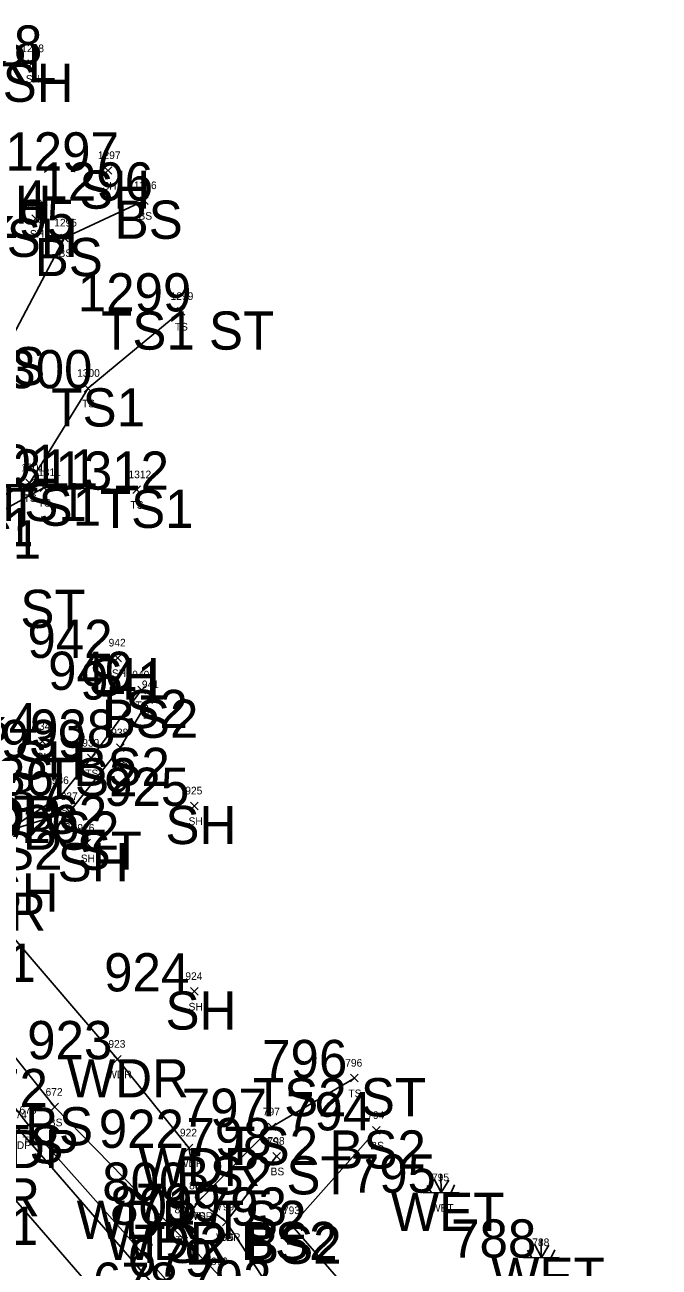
# Model space of a CAD drawing. Extents: x 1616840 to 1618410, y 488554 to 491945.
# Drawn here: x 1617896.5 to 1618062.6, y 488979.2 to 489304.3 of the extents above; entities that cross this region are included whole.
import ezdxf

# ---------------------------------------------------------------- set-up
doc = ezdxf.new("R2010")
doc.units = 0
for name, color, linetype in [('C_A', 7, 'Continuous'), ('C_I', 7, 'Continuous'), ('L_A', 7, 'Continuous'), ('L_I', 7, 'Continuous'), ('L_TIC', 7, 'Continuous'), ('LAWA', 7, 'Continuous'), ('LELB', 7, 'Continuous'), ('LWET', 7, 'Continuous'), ('P_A', 7, 'Continuous'), ('P_I', 7, 'Continuous'), ('PET', 7, 'Continuous'), ('PRC', 7, 'Continuous')]:
    doc.layers.add(name, color=color, linetype=linetype)

msp = doc.modelspace()

# ---------------------------------------------------------------- linework, layer by layer
at = {"layer": 'L_TIC'}
for points in [[(1617897.27, 489293.2), (1617899.27, 489295.2)], [(1617899.27, 489293.2), (1617897.27, 489295.2)], [(1617917.32, 489265.23), (1617919.32, 489267.23)], [(1617919.32, 489265.23), (1617917.32, 489267.23)], [(1617926.82, 489257.36), (1617928.82, 489259.36)], [(1617928.82, 489257.36), (1617926.82, 489259.36)], [(1617898.33, 489252.62), (1617900.33, 489254.62)], [(1617900.33, 489252.62), (1617898.33, 489254.62)], [(1617905.89, 489247.58), (1617907.89, 489249.58)], [(1617907.89, 489247.58), (1617905.89, 489249.58)], [(1617936.38, 489228.35), (1617938.38, 489230.35)], [(1617938.38, 489228.35), (1617936.38, 489230.35)], [(1617912.05, 489208.24), (1617914.05, 489210.24)], [(1617914.05, 489208.24), (1617912.05, 489210.24)], [(1617896.8, 489183.49), (1617898.8, 489185.49)], [(1617898.8, 489183.49), (1617896.8, 489185.49)], [(1617900.54, 489182.26), (1617902.54, 489184.26)], [(1617902.54, 489182.26), (1617900.54, 489184.26)], [(1617924.77, 489181.7), (1617926.77, 489183.7)], [(1617926.77, 489181.7), (1617924.77, 489183.7)], [(1617919.82, 489137.67), (1617921.82, 489139.67)], [(1617921.82, 489137.67), (1617919.82, 489139.67)], [(1617926.08, 489129.32), (1617928.08, 489131.32)], [(1617928.08, 489129.32), (1617926.08, 489131.32)], [(1617927.95, 489126.77), (1617929.95, 489128.77)], [(1617929.95, 489126.77), (1617927.95, 489128.77)], [(1617900.09, 489115.84), (1617902.09, 489117.84)], [(1617902.09, 489115.84), (1617900.09, 489117.84)], [(1617912.91, 489111.46), (1617914.91, 489113.46)], [(1617914.91, 489111.46), (1617912.91, 489113.46)], [(1617920.49, 489114.18), (1617922.49, 489116.18)], [(1617922.49, 489114.18), (1617920.49, 489116.18)], [(1617904.98, 489101.66), (1617906.98, 489103.66)], [(1617906.98, 489101.66), (1617904.98, 489103.66)], [(1617939.88, 489098.96), (1617941.88, 489100.96)], [(1617941.88, 489098.96), (1617939.88, 489100.96)], [(1617907.26, 489097.48), (1617909.26, 489099.48)], [(1617909.26, 489097.48), (1617907.26, 489099.48)], [(1617911.68, 489089.21), (1617913.68, 489091.21)], [(1617913.68, 489089.21), (1617911.68, 489091.21)], [(1617939.89, 489050.41), (1617941.89, 489052.41)], [(1617941.89, 489050.41), (1617939.89, 489052.41)], [(1617919.74, 489032.67), (1617921.74, 489034.67)], [(1617921.74, 489032.67), (1617919.74, 489034.67)], [(1617981.81, 489027.72), (1617983.81, 489029.72)], [(1617983.81, 489027.72), (1617981.81, 489029.72)], [(1617903.35, 489020.12), (1617905.35, 489022.12)], [(1617905.35, 489020.12), (1617903.35, 489022.12)], [(1617896.51, 489015.41), (1617898.51, 489017.41)], [(1617898.51, 489015.41), (1617896.51, 489017.41)], [(1617960.2, 489014.97), (1617962.2, 489016.97)], [(1617962.2, 489014.97), (1617960.2, 489016.97)], [(1617987.53, 489014.04), (1617989.53, 489016.04)], [(1617989.53, 489014.04), (1617987.53, 489016.04)], [(1617938.48, 489009.46), (1617940.48, 489011.46)], [(1617940.48, 489009.46), (1617938.48, 489011.46)], [(1617961.42, 489007.28), (1617963.42, 489009.28)], [(1617963.42, 489007.28), (1617961.42, 489009.28)], [(1617941.05, 488995.62), (1617943.05, 488997.62)], [(1617943.05, 488995.62), (1617941.05, 488997.62)], [(1617941.05, 488995.62), (1617943.05, 488997.62)], [(1617943.05, 488995.62), (1617941.05, 488997.62)], [(1617936.58, 488989.34), (1617938.58, 488991.34)], [(1617938.58, 488989.34), (1617936.58, 488991.34)], [(1617948.25, 488990.1), (1617950.25, 488992.1)], [(1617950.25, 488990.1), (1617948.25, 488992.1)], [(1617948.25, 488990.1), (1617950.25, 488992.1)], [(1617950.25, 488990.1), (1617948.25, 488992.1)], [(1617965.46, 488989.12), (1617967.46, 488991.12)], [(1617967.46, 488989.12), (1617965.46, 488991.12)]]:
    msp.add_lwpolyline(points, dxfattribs=at)
at = {"layer": 'LAWA'}
msp.add_lwpolyline([(1618054.11, 488878.94), (1618032.56, 488908.22), (1617984.5, 488948.81), (1617962.42, 488971.02), (1617949.25, 488991.1), (1617942.05, 488996.62), (1617939.48, 489010.46), (1617920.74, 489033.67), (1617883.34, 489077.27), (1617877.68, 489088.61), (1617878.38, 489093.84), (1617887.44, 489102.52), (1617873.22, 489118.9), (1617851.23, 489131.15), (1617838.03, 489154.89), (1617849.15, 489173.78), (1617849.34, 489195.24), (1617843.77, 489224.33)], dxfattribs=at)
msp.add_lwpolyline([(1618054.11, 488878.94), (1618032.56, 488908.22), (1617984.5, 488948.81), (1617962.42, 488971.02), (1617949.25, 488991.1), (1617942.05, 488996.62), (1617939.48, 489010.46), (1617920.74, 489033.67), (1617883.34, 489077.27), (1617877.68, 489088.61), (1617878.38, 489093.84), (1617887.44, 489102.52), (1617873.22, 489118.9), (1617851.23, 489131.15), (1617838.03, 489154.89), (1617849.15, 489173.78), (1617849.34, 489195.24), (1617843.77, 489224.33)], dxfattribs=at)
at = {"layer": 'LELB'}
for points in [[(1617849.15, 489173.78), (1617871.43, 489197.51), (1617891.8, 489220.04), (1617906.89, 489248.58), (1617927.82, 489258.36)], [(1617849.15, 489173.78), (1617871.43, 489197.51), (1617891.8, 489220.04), (1617906.89, 489248.58), (1617927.82, 489258.36)], [(1617937.38, 489229.35), (1617913.05, 489209.24), (1617897.8, 489184.49), (1617883.85, 489177.92), (1617867.18, 489172.75), (1617853.37, 489162.68), (1617842.12, 489158.62), (1617843.24, 489156.42), (1617853.89, 489159.37), (1617866.1, 489166.17), (1617873.77, 489168.84), (1617885.84, 489174.65), (1617901.54, 489183.26), (1617925.77, 489182.7)], [(1617937.38, 489229.35), (1617913.05, 489209.24), (1617897.8, 489184.49), (1617883.85, 489177.92), (1617867.18, 489172.75), (1617853.37, 489162.68), (1617842.12, 489158.62), (1617843.24, 489156.42), (1617853.89, 489159.37), (1617866.1, 489166.17), (1617873.77, 489168.84), (1617885.84, 489174.65), (1617901.54, 489183.26), (1617925.77, 489182.7)], [(1617891.53, 489093.24), (1617905.98, 489102.66), (1617913.91, 489112.46), (1617927.08, 489130.32)], [(1617891.53, 489093.24), (1617905.98, 489102.66), (1617913.91, 489112.46), (1617927.08, 489130.32)], [(1617891.53, 489093.24), (1617908.26, 489098.48), (1617921.49, 489115.18), (1617928.95, 489127.77)], [(1617891.53, 489093.24), (1617908.26, 489098.48), (1617921.49, 489115.18), (1617928.95, 489127.77)], [(1617879.81, 489051.85), (1617904.35, 489021.12), (1617947.62, 488976.78), (1617977.61, 488946.51), (1618015.66, 488908.18), (1618041.03, 488885.14), (1618075.84, 488847.6), (1618086.99, 488829.82), (1618109.76, 488805.64), (1618148.46, 488775.15)], [(1617879.81, 489051.85), (1617904.35, 489021.12), (1617947.62, 488976.78), (1617977.61, 488946.51), (1618015.66, 488908.18), (1618041.03, 488885.14), (1618075.84, 488847.6), (1618086.99, 488829.82), (1618109.76, 488805.64), (1618148.46, 488775.15)], [(1617873.66, 489046.89), (1617897.51, 489016.41), (1617938.42, 488970.46), (1617969.5, 488937.69), (1618005.95, 488898.76), (1618030.22, 488874.79), (1618079.27, 488832.72), (1618108.55, 488803.91)], [(1617873.66, 489046.89), (1617897.51, 489016.41), (1617938.42, 488970.46), (1617969.5, 488937.69), (1618005.95, 488898.76), (1618030.22, 488874.79), (1618079.27, 488832.72), (1618108.55, 488803.91)], [(1617982.81, 489028.72), (1617961.2, 489015.97), (1617942.05, 488996.62), (1617937.58, 488990.34)], [(1617982.81, 489028.72), (1617961.2, 489015.97), (1617942.05, 488996.62), (1617937.58, 488990.34)], [(1617998.64, 488953.14), (1617966.46, 488990.12), (1617988.53, 489015.04)], [(1617998.64, 488953.14), (1617966.46, 488990.12), (1617988.53, 489015.04)], [(1617962.42, 489008.28), (1617949.25, 488991.1)], [(1617962.42, 489008.28), (1617949.25, 488991.1)]]:
    msp.add_lwpolyline(points, dxfattribs=at)
at = {"layer": 'LWET'}
for p, q in [((1618005.48, 488998.74), (1618005.45, 489003.48)), ((1618001.87, 489000.65), (1618003.03, 488998.72)), ((1618003.69, 489002.3), (1618005.51, 488998.77)), ((1618007.5, 489002.02), (1618005.51, 488998.77)), ((1618008.98, 489000.81), (1618008.1, 488998.77)), ((1618000.82, 488998.72), (1618010.2, 488998.77)), ((1618005.63, 488998.93), (1618005.51, 488998.93)), ((1618031.74, 488981.75), (1618031.71, 488986.49)), ((1618028.13, 488983.65), (1618029.29, 488981.72)), ((1618029.95, 488985.3), (1618031.77, 488981.77)), ((1618033.75, 488985.03), (1618031.77, 488981.77)), ((1618035.24, 488983.81), (1618034.36, 488981.77)), ((1618027.08, 488981.72), (1618036.45, 488981.77)), ((1618031.89, 488981.93), (1618031.77, 488981.93))]:
    msp.add_line(p, q, dxfattribs=at)
at = {"layer": 'PET'}
msp.add_lwpolyline([(1617872.01, 489044.99), (1617894.99, 489015.16), (1617935.77, 488968.16), (1617966.34, 488935.71), (1618003.97, 488896.99), (1618028.35, 488873.06), (1618077.06, 488828.57), (1618108.12, 488802.11), (1618146.01, 488772.77)], dxfattribs=at)
msp.add_lwpolyline([(1617872.01, 489044.99), (1617894.99, 489015.16), (1617935.77, 488968.16), (1617966.34, 488935.71), (1618003.97, 488896.99), (1618028.35, 488873.06), (1618077.06, 488828.57), (1618108.12, 488802.11), (1618146.01, 488772.77)], dxfattribs=at)
at = {"layer": 'PRC'}
msp.add_lwpolyline([(1617862.02, 489037.03), (1617888.99, 489002.53), (1617926.01, 488959.87), (1617957.81, 488925.53), (1617994.59, 488887.79), (1618019.67, 488863.32), (1618068.7, 488818.39), (1618098.08, 488793.55), (1618137.08, 488762.99)], dxfattribs=at)
msp.add_lwpolyline([(1617862.02, 489037.03), (1617888.99, 489002.53), (1617926.01, 488959.87), (1617957.81, 488925.53), (1617994.59, 488887.79), (1618019.67, 488863.32), (1618068.7, 488818.39), (1618098.08, 488793.55), (1618137.08, 488762.99)], dxfattribs=at)

# ---------------------------------------------------------------- texts
at = {"layer": 'C_A'}
for s, p in [('RVRL', (1617869.06, 489289.31)), ('SH', (1617890.71, 489284.2)), ('SH', (1617910.76, 489256.23)), ('SH', (1617884.94, 489252.3)), ('BS', (1617920.02, 489248.36)), ('SH', (1617891.77, 489243.62)), ('BS', (1617899.1, 489238.58)), ('TS1 ST', (1617916.48, 489219.35)), ('BS', (1617884.01, 489210.04)), ('TS1', (1617903.45, 489199.24)), ('TS1', (1617888.19, 489174.49)), ('TS1', (1617891.94, 489173.26)), ('TS1', (1617916.17, 489172.7)), ('TS1', (1617874.25, 489167.92)), ('TS1', (1617876.24, 489164.65)), ('BS2 ST', (1617866.34, 489146.51)), ('SH', (1617913.26, 489128.67)), ('TS2', (1617914.64, 489120.32)), ('BS2', (1617916.67, 489117.77)), ('SH', (1617893.53, 489106.84)), ('BS2', (1617909.21, 489105.18)), ('TS2', (1617901.47, 489102.46)), ('WDR', (1617874.25, 489092.52)), ('TS2', (1617893.54, 489092.66)), ('BS2', (1617895.98, 489088.48)), ('SH', (1617933.32, 489089.96)), ('BS2 ST TS2 ST', (1617832.05, 489083.24)), ('SH', (1617905.12, 489080.21)), ('SH', (1617886.78, 489072.28)), ('WDR', (1617870.15, 489067.27)), ('BS ST JT 671', (1617816.12, 489053.88)), ('SH', (1617933.33, 489041.41)), ('WDR', (1617907.55, 489023.67)), ('TS2 ST', (1617956.24, 489018.72)), ('BS', (1617896.55, 489011.12)), ('TS', (1617889.55, 489006.41)), ('TS2', (1617948.76, 489005.97)), ('RDP', (1617882.43, 489005.16)), ('BS2', (1617976.24, 489005.04)), ('WDR', (1617926.29, 489000.46)), ('BS2 ST', (1617936, 488998.28)), ('CR', (1617881.16, 488992.53)), ('WDR TS2', (1617910.08, 488986.62)), ('WET', (1617992.37, 488988.74)), ('RDP1', (1617864.35, 488985.05)), ('WDR BS2', (1617917.44, 488981.1)), ('TS2', (1617925.14, 488980.34)), ('BS2', (1617954.18, 488980.12)), ('WET', (1618018.63, 488971.75))]:
    msp.add_text(s, height=10, dxfattribs=at).set_placement(p)
at = {"layer": 'C_I'}
for s, p in [('1298', (1617871.34, 489294.2)), ('1297', (1617891.39, 489266.23)), ('1296', (1617900.34, 489258.36)), ('1294', (1617872.4, 489253.62)), ('1295', (1617879.96, 489248.58)), ('1299', (1617910.37, 489229.35)), ('1300', (1617884.47, 489209.24)), ('1301', (1617875.75, 489184.49)), ('1311', (1617885.95, 489183.26)), ('1312', (1617904.51, 489182.7)), ('942', (1617897.19, 489138.67)), ('940', (1617902.6, 489130.32)), ('941', (1617911, 489127.77)), ('934', (1617877.47, 489116.84)), ('938', (1617897.87, 489115.18)), ('939', (1617890.21, 489112.46)), ('936', (1617881.8, 489102.66)), ('925', (1617917.26, 489099.96)), ('937', (1617884.64, 489098.48)), ('926', (1617888.5, 489090.21)), ('924', (1617917.27, 489051.41)), ('923', (1617897.12, 489033.67)), ('796', (1617958.64, 489028.72)), ('672', (1617880.25, 489021.12)), ('797', (1617937.58, 489015.97)), ('794', (1617964.91, 489015.04)), ('922', (1617915.86, 489010.46)), ('798', (1617938.8, 489008.28)), ('800', (1617916.77, 488996.62)), ('795', (1617981.86, 488998.74)), ('801', (1617918.84, 488990.34)), ('799', (1617925.55, 488991.1)), ('793', (1617942.84, 488990.12)), ('788', (1618008.12, 488981.75)), ('679', (1617923.45, 488976.78)), ('678', (1617914.32, 488970.46)), ('792', (1617938.8, 488971.02))]:
    msp.add_text(s, height=10, dxfattribs=at).set_placement(p)
at = {"layer": 'L_A'}
for s, p in [('SH', (1617896.76, 489289.2)), ('SH', (1617916.81, 489261.23)), ('BS', (1617926.26, 489253.36)), ('SH', (1617897.82, 489248.62)), ('BS', (1617905.33, 489243.58)), ('TS', (1617935.79, 489224.35)), ('TS', (1617911.46, 489204.24)), ('TS', (1617896.2, 489179.49)), ('TS', (1617899.95, 489178.26)), ('TS', (1617924.18, 489177.7)), ('SH', (1617919.3, 489133.67)), ('TS', (1617925.49, 489125.32)), ('BS', (1617927.39, 489122.77)), ('SH', (1617899.58, 489111.84)), ('BS', (1617919.94, 489110.18)), ('TS', (1617912.32, 489107.46)), ('TS', (1617904.39, 489097.66)), ('BS', (1617906.7, 489093.48)), ('SH', (1617939.37, 489094.96)), ('SH', (1617911.16, 489085.21)), ('SH', (1617939.38, 489046.41)), ('WDR', (1617918.1, 489028.67)), ('TS', (1617981.22, 489023.72)), ('BS', (1617902.79, 489016.12)), ('TS', (1617895.92, 489011.41)), ('TS', (1617959.61, 489010.97)), ('BS', (1617986.97, 489010.04)), ('WDR', (1617936.84, 489005.46)), ('BS', (1617960.86, 489003.28)), ('WDR', (1617939.41, 488991.62)), ('TS', (1617940.46, 488991.62)), ('WET', (1618002.86, 488993.74)), ('TS', (1617935.99, 488985.34)), ('WDR', (1617946.61, 488986.1)), ('BS', (1617947.69, 488986.1)), ('BS', (1617964.91, 488985.12))]:
    msp.add_text(s, height=2, dxfattribs=at).set_placement(p)
at = {"layer": 'L_I'}
for s, p in [('1298', (1617895.57, 489297.2)), ('1297', (1617915.63, 489269.23)), ('1296', (1617925.07, 489261.36)), ('1294', (1617896.63, 489256.62)), ('1295', (1617904.2, 489251.58)), ('1299', (1617934.68, 489232.35)), ('1300', (1617910.2, 489212.24)), ('1301', (1617895.59, 489187.49)), ('1311', (1617899.99, 489186.26)), ('1312', (1617923.65, 489185.7)), ('942', (1617918.45, 489141.67)), ('940', (1617924.64, 489133.32)), ('941', (1617927.16, 489130.77)), ('934', (1617898.73, 489119.84)), ('938', (1617919.13, 489118.18)), ('939', (1617911.54, 489115.46)), ('936', (1617903.56, 489105.66)), ('925', (1617938.52, 489102.96)), ('937', (1617905.9, 489101.48)), ('926', (1617910.26, 489093.21)), ('924', (1617938.53, 489054.41)), ('923', (1617918.38, 489036.67)), ('796', (1617980.4, 489031.72)), ('672', (1617901.94, 489024.12)), ('673', (1617895.1, 489019.41)), ('797', (1617958.84, 489018.97)), ('794', (1617986.17, 489018.04)), ('922', (1617937.12, 489013.46)), ('798', (1617960.06, 489011.28)), ('795', (1618003.12, 489001.74)), ('800', (1617939.52, 488999.62)), ('800', (1617939.52, 488999.62)), ('801', (1617935.71, 488993.34)), ('799', (1617946.88, 488994.1)), ('799', (1617946.88, 488994.1)), ('793', (1617964.1, 488993.12)), ('788', (1618029.38, 488984.75)), ('679', (1617945.2, 488979.78))]:
    msp.add_text(s, height=2, dxfattribs=at).set_placement(p)
at = {"layer": 'P_A'}
msp.add_text('RDP', height=2, dxfattribs=at).set_placement((1617892.47, 489010.16))
at = {"layer": 'P_I'}
msp.add_text('674', height=2, dxfattribs=at).set_placement((1617892.58, 489018.16))

doc.saveas('drawing.dxf')
